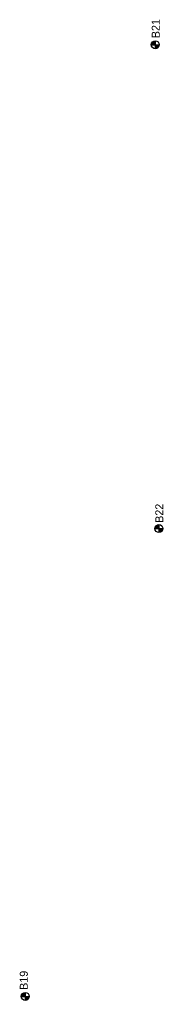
# Model space of a CAD drawing. Extents: x 345549 to 379569, y 127949 to 230467.
# Drawn here: x 361288 to 361467, y 139155 to 140380 of the extents above; entities that cross this region are included whole.
import ezdxf

# ---------------------------------------------------------------- set-up
doc = ezdxf.new("R2010")
doc.units = 0
doc.layers.add('E_SOIL_BORE2 [KAPUR_CADDS_LEVELS]', color=7, linetype='Continuous')
doc.layers.add('P_MARK', color=7, linetype='Continuous')

msp = doc.modelspace()

# ---------------------------------------------------------------- linework, layer by layer
at = {"layer": 'P_MARK'}
for p, q in [((361457.1, 140353.7), (361457, 140343.7)), ((361452.1, 140348.7), (361462, 140348.7)), ((361456.7, 139744.2), (361466.7, 139744.2)), ((361461.7, 139749.2), (361461.7, 139739.2)), ((361294.9, 139164.7), (361294.9, 139154.7)), ((361289.9, 139159.7), (361299.9, 139159.7))]:
    msp.add_line(p, q, dxfattribs=at)
for centre in [(361457.1, 140348.7), (361461.7, 139744.2), (361294.9, 139159.7)]:
    msp.add_circle(centre, 5, dxfattribs=at)
for centre, radius, start, end in [((361457.1, 140348.7), 4.5, 89.9869, 179.9869), ((361457.1, 140348.7), 4, 89.9869, 179.9869), ((361457.1, 140348.7), 3.5, 89.9869, 179.9869), ((361457.1, 140348.7), 3, 89.9869, 179.9869), ((361457.1, 140348.7), 2.5, 89.9869, 179.9869), ((361457.1, 140348.7), 2, 89.9869, 179.9869), ((361457.1, 140348.7), 1.5, 89.9869, 179.9869), ((361457.1, 140348.7), 1, 89.9869, 179.9869), ((361457.1, 140348.7), 0.5, 89.9869, 179.9869), ((361457.1, 140348.7), 4.5, 269.9869, 359.9869), ((361457.1, 140348.7), 4, 269.9869, 359.9869), ((361457.1, 140348.7), 3.5, 269.9869, 359.9869), ((361457.1, 140348.7), 3, 269.9869, 359.9869), ((361457.1, 140348.7), 2.5, 269.9869, 359.9869), ((361457.1, 140348.7), 2, 269.9869, 359.9869), ((361457.1, 140348.7), 1.5, 269.9869, 359.9869), ((361457.1, 140348.7), 1, 269.9869, 359.9869), ((361457.1, 140348.7), 0.5, 269.9869, 359.9869), ((361461.7, 139744.2), 4.5, 89.9869, 179.9869), ((361461.7, 139744.2), 4, 89.9869, 179.9869), ((361461.7, 139744.2), 3.5, 89.9869, 179.9869), ((361461.7, 139744.2), 3, 89.9869, 179.9869), ((361461.7, 139744.2), 2.5, 89.9869, 179.9869), ((361461.7, 139744.2), 2, 89.9869, 179.9869), ((361461.7, 139744.2), 1.5, 89.9869, 179.9869), ((361461.7, 139744.2), 1, 89.9869, 179.9869), ((361461.7, 139744.2), 0.5, 89.9869, 179.9869), ((361461.7, 139744.2), 4.5, 269.9869, 359.9869), ((361461.7, 139744.2), 4, 269.9869, 359.9869), ((361461.7, 139744.2), 3.5, 269.9869, 359.9869), ((361461.7, 139744.2), 3, 269.9869, 359.9869), ((361461.7, 139744.2), 2.5, 269.9869, 359.9869), ((361461.7, 139744.2), 2, 269.9869, 359.9869), ((361461.7, 139744.2), 1.5, 269.9869, 359.9869), ((361461.7, 139744.2), 1, 269.9869, 359.9869), ((361461.7, 139744.2), 0.5, 269.9869, 359.9869), ((361294.9, 139159.7), 4.5, 89.9869, 179.9869), ((361294.9, 139159.7), 4, 89.9869, 179.9869), ((361294.9, 139159.7), 3.5, 89.9869, 179.9869), ((361294.9, 139159.7), 3, 89.9869, 179.9869), ((361294.9, 139159.7), 2.5, 89.9869, 179.9869), ((361294.9, 139159.7), 2, 89.9869, 179.9869), ((361294.9, 139159.7), 1.5, 89.9869, 179.9869), ((361294.9, 139159.7), 1, 89.9869, 179.9869), ((361294.9, 139159.7), 0.5, 89.9869, 179.9869), ((361294.9, 139159.7), 4.5, 269.9869, 359.9869), ((361294.9, 139159.7), 4, 269.9869, 359.9869), ((361294.9, 139159.7), 3.5, 269.9869, 359.9869), ((361294.9, 139159.7), 3, 269.9869, 359.9869), ((361294.9, 139159.7), 2.5, 269.9869, 359.9869), ((361294.9, 139159.7), 2, 269.9869, 359.9869), ((361294.9, 139159.7), 1.5, 269.9869, 359.9869), ((361294.9, 139159.7), 1, 269.9869, 359.9869), ((361294.9, 139159.7), 0.5, 269.9869, 359.9869)]:
    msp.add_arc(centre, radius, start, end, dxfattribs=at)

# ---------------------------------------------------------------- texts
at = {"layer": 'E_SOIL_BORE2 [KAPUR_CADDS_LEVELS]'}
for s, p in [('B21', (361462.7, 140356.9)), ('B22', (361467.2, 139751.4)), ('B19', (361298.1, 139167.9))]:
    msp.add_text(s, height=10, rotation=89.9869, dxfattribs=at).set_placement(p)

doc.saveas('drawing.dxf')
